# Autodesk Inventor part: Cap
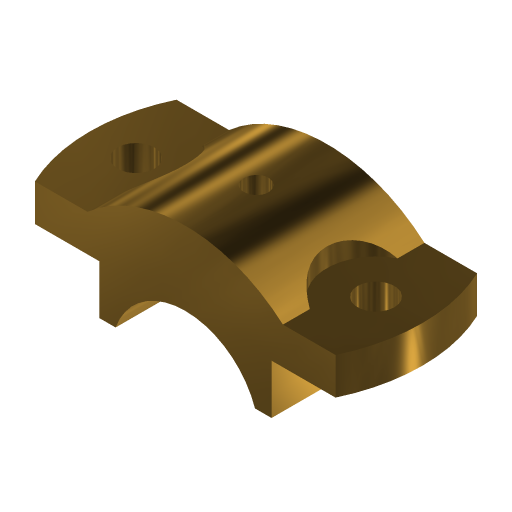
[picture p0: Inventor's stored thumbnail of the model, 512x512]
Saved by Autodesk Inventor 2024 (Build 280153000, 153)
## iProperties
Created: 2009-04
Part Number: Cap
Document SubType Name: Modeling
Designer: Sham
Density: 8.47 g/cm^3
Material: Brass, Soft Yellow
Appearance: Brass - Satin
Author: Sham
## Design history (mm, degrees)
sketch "Sketch1"
  geometry: L1 (-48.857, 23)-(48.857, 23); L2 (48.857, -23)-(-48.857, -23); A1 r 54 centre (0, 0) between (-48.857, 23) and (-48.857, -23); A2 r 54 centre (0, 0) between (48.857, -23) and (48.857, 23); 1 further point
  constraints: 4 end point, 4 point on circle, 2 centre point, 2 coincident, 1 horizontal, 1 parallel, 1 other
  dimensions: "d3" = 54 radius of A1; "d4" = 54 radius of A2; "d5" = 46 distance between parallel lines of L2 L1; "d6" = 23 distance from line of point (0, 0) L1
extrude "Extrusion1" new body sketch "Sketch1" distance "d7" = 12; taper "d8" = 0 deg
sketch "Sketch3"
  geometry: L1 (20.906, 0)-(20.906, -16); L2 (76.906, -0.137)-(76.906, -16.137); L3 (20.906, -16)-(26.23, -16); L4 (71.532, -16.137)-(76.906, -16.137); L5 (76.906, -0.137)-(76.857, 12); L6 (97.714, 0)-(0, 0) reference; L7 (76.857, 12)-(80.606, 12); L8 (17.108, 12)-(20.906, 12); L9 (20.906, 12)-(20.906, 0); L10 (0, 12)-(97.714, 12) reference; A1 r 24 centre (48.857, -24) between (71.532, -16.137) and (26.23, -16); A2 r 48 centre (48.857, -24) between (80.606, 12) and (17.108, 12); 3 further points
  constraints: 16 end point, 4 point on circle, 3 parallel, 3 perpendicular, 2 centre point, 2 coincident, 2 vertical alignment, 1 collinear, 1 midpoint, 1 vertical, 2 other
  dimensions: "d17" = 48 diameter of A1; "d18" = 16 distance of L1.start L1.end; "d19" = 56 distance between parallel lines of L2 L1; "d21" = 8 vertical distance of A1.centre L1.end; "d22" = 48 radius of A2; "d23" = 0 distance from line of L6 L1.start; "d38" = 31.74902 distance of L7.end point (48.857, 12); "d39" = 28 distance from line of point (48.857, 12) L5
extrude "Extrusion2" join sketch "Sketch3" stored distance "d24" = 12; taper "d25" = 0 deg
sketch "Sketch4"
  geometry: 2 further points
  dimensions: "d26" = 78 distance of point (39, 0) point (-39, 0)
hole "Hole1" sketch "Sketch4" at (-39, 0), (39, 0) diameter "d28" = 12; stored, may be unused: countersink angle "d32" = 90 deg, drill point angle "d34" = 118 deg; dims "d29" = 6, "d30" = 4, "d31" = 2, "d33" = 8
sketch "Sketch5"
  geometry: L1 (-31.749, -23)-(-31.749, 23) reference; L2 (-31.749, 14.263)-(-31.749, -14.263); C1 r 6 at (-39, 0) reference; A1 r 16 centre (-39, 0) between (-31.749, -14.263) and (-31.749, 14.263)
  constraints: 2 end point, 2 point on circle, 1 centre point, 1 coincident, 1 collinear, 1 point on line
  dimensions: "d35" = 16 radius of A1
extrude "Extrusion3" cut sketch "Sketch5" distance "d36" = 12; taper "d37" = 0 deg
mirror "Mirror2"
workplane "Work Plane4"
sketch "Sketch6"
  geometry: L1 (-31.749, 0)-(31.749, 0) reference; 1 further point
  dimensions: "d40" = 23 distance from line of L1 point (0, 23)
hole "Hole2" sketch "Sketch6" at (0, 23) diameter "d41" = 6; stored, may be unused: countersink angle "d45" = 90 deg, drill point angle "d47" = 118 deg; dims "d42" = 6, "d43" = 8, "d44" = 16, "d46" = 8
body "Solid1"
